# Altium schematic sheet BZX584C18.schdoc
size 127 x 101 mm
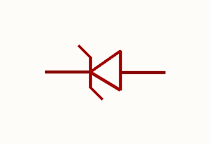
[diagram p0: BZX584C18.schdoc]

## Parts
D?  bzx584c18  [SOD-523_L1.2-W0.8-LS1.6-RD]  (value not drawn)

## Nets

Not connected (* = marked no-connect by the designer): D? 1(C) 2(A)

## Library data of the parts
D? = bzx584c18: 二极管配置:1个独立式;稳压值(标称值):18V;稳压值(范围值):16.8V~19.1V;耗散功率(Pd):150mW;; Manufacturer: CJ(江苏长电/长晶); AddInBom: yes; ModelId: 8f56a03db567494d8f4c9d12aa52a741; ModelName: SOD-523_L1.2-W0.8-H0.7-LS1.6; ModelTransform: 62.992,31.496,0,180,0,0,0,0,0; Diode Configuration: 1个独立式; Zener Voltage(Nom): 18V; Reverse Leakage Current (Ir): 100nA; Pd - Power Dissipation: 150mW; Impedance(Zzt): 45Ω; Impedance(Zzk): 225Ω; Operating Junction Temperature Range: -55℃~+150℃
